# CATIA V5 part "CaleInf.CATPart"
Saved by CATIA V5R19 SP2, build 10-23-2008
Part number: CaleInf
Bounding box of the stored display mesh (mm): x 0 to 15, y 0 to 50, z 0 to 20
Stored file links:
  D:\SCHOOL\FRANCE\BANC_POUTRE_EN_MOUSSE\CaleInf.CATPart
  C:\Program Files\Dassault Systemes\B19\intel_a\reffiles\standard\MetricThickPitch.txt
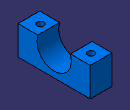
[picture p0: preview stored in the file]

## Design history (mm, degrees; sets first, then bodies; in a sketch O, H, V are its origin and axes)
AxisSystem1: origin (0, 0, 0), X (1, 0, 0), Y (0, 1, 0), Z (0, 0, 1)
Body1 (main body)
  Sketch1 on YZ plane of AxisSystem1, origin (0, 0, 0), H (0, 1, 0), V (0, 0, 1)
    line L1 (0, 0) -> (50, 0)
    line L2 (50, 0) -> (50, 20)
    line L3 (50, 20) -> (0, 20)
    line L4 (0, 20) -> (0, 0)
    length L3 = 50
    length L2 = 20
    horizontal: L1 H, L3 H
    vertical: L2 V, L4 V
  Pad1: profile Sketch1, direction (1, 0, 0), length 15
  Sketch2 on end face of Pad1, origin (15, 0, 0), H (0, 1, 0), V (0, 0, 1)
    point P1 (25, 16)
    reference projected line E1 (0, 14) -> (0, 0) from edge [face of Pad1 from Sketch1.L4 | end face of Pad1]
    arc A1 centre (25, 16) radius 12 from (13.6863, 20) to (36.3137, 20) ccw
    point P2 (13.6863, 20)
    point P3 (36.3137, 20)
    reference projected line E2 (50, 20) -> (0, 20) from edge [face of Pad1 from Sketch1.L3 | end face of Pad1]
    reference projected line E3 (50, 20) -> (0, 20) from edge [face of Pad1 from Sketch1.L3 | end face of Pad1]
    projected line E4 (50, 20) -> (0, 20) from edge [face of Pad1 from Sketch1.L3 | end face of Pad1]
    projected line E5 (36.3137, 20) -> (13.6863, 20) from edge [face of Pad1 from Sketch1.L3 | end face of Pad1]
    axis line L1 (-1.3656, 16) -> (62.238, 16)
    distance P1 E1 = 25
    radius A1 = 12
    distance E4 L1 = 4
    coincidence: P2 E2, P3 E3, P1 L1
    horizontal: L1 H
  Pocket1: profile Sketch2, direction (-1, 0, 0), through (limit type 6)
  Sketch3 on face of Pad1 from Sketch1.L3, origin (8.2003, 5.6664, 20), H (1, 0, 0), V (0, 1, 0)
    point P1 (-0.7003, 2.3336)
    axis line L1 (-0.7003, 51.9597) -> (-0.7003, -13.6449)
    reference projected line E1 (6.7997, 44.3336) -> (6.7997, -5.6664) from edge [face of Pad1 from Sketch1.L3 | end face of Pad1]
    reference projected line E2 (-8.2003, 44.3336) -> (-8.2003, -5.6664) from edge [start face of Pad1 | face of Pad1 from Sketch1.L3]
    reference projected line E3 (-8.2003, -5.6664) -> (6.7997, -5.6664) from edge [face of Pad1 from Sketch1.L4 | face of Pad1 from Sketch1.L3]
    distance E3 P1 = 8
    vertical: L1 V
    symmetry: E1 E2 L1
    coincidence: P1 L1
  Hole1: placed by Sketch3, at (7.5, 8, 20) direction (0, 0, -1), diameter 4.917, depth 10, threaded "M6", thread diameter 6, thread depth 10, pitch 1
  RectPattern1: of Hole1, direction 1 instances 2, spacing 35, along edge [face of Pad1 from Sketch1.L3 | end face of Pad1] reversed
